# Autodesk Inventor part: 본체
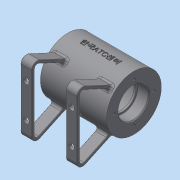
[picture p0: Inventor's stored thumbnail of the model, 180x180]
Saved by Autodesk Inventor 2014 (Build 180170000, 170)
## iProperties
Created: 2021-12
Part Number: 본체
Material: 일반
Document SubType Name: Modeling
Designer: dg
Density: 1 g/cm^3
Appearance: 기본값
Author: dg
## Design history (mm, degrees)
sketch "스케치1"
  geometry: L1 (-35, 0)-(35, 0); L2 (-35, 16)-(-23, 16); L3 (-23, 16)-(-23, 14); L4 (-23, 14)-(-21, 14); L5 (-21, 14)-(-21, 21); L6 (-21, 21)-(21, 21); L7 (21, 21)-(21, 14); L8 (21, 14)-(23, 14); L9 (23, 14)-(23, 16); L10 (23, 16)-(35, 16); L11 (35, 16)-(35, 29); L12 (35, 29)-(-35, 29); L13 (-35, 29)-(-35, 16); 2 further points
  constraints: 26 end point, 9 parallel, 3 collinear, 2 horizontal alignment, 2 perpendicular, 2 vertical alignment, 1 coincident, 1 horizontal, 1 midpoint
  dimensions: "d0" = 70 distance of L1.start L1.end; "d1" = 32 diameter of L2 L1; "d2" = 28 diameter of L4 L1; "d3" = 42 diameter of L6 L1; "d4" = 58 diameter of L12 L1; "d5" = 12 distance of L2.start L2.end; "d7" = 42 distance of L5.end L6.end
revolve "회전1" sketch "스케치1" stored, may be unused: angle "d8" = 90 deg
node "작업 평면1"
sketch "스케치2"
  geometry: L1 (-22.743, -17.993)-(-40, -55); L2 (-40, -55)-(40, -55); L3 (40, -55)-(22.743, -17.993); L4 (-20.574, -20.438)-(-35.291, -52); L5 (-35.291, -52)-(35.291, -52); L6 (35.291, -52)-(20.574, -20.438); A1 r 29 centre (0, 0) between (-22.743, -17.993) and (22.743, -17.993) reference; 1 further point
  constraints: 12 end point, 4 point on circle, 3 parallel, 2 horizontal alignment, 1 horizontal
  dimensions: "d10" = 80 distance of L2.end L1.end; "d11" = 3 distance between parallel lines of L4 L1; "d12" = 3 distance between parallel lines of L3 L6; "d13" = 3 distance between parallel lines of L2 L5; "d14" = 55 distance from line of L2 point (0, 0); "d15" = 65 deg angle of L2 L3
extrude "돌출1" join sketch "스케치2" distance "d16" = 12; taper "d17" = 0 deg
node "작업 평면2"
fillet "모깎기1" dims "d18" = 6, "d19" = 3
sketch "스케치3"
  geometry: C1 r 29 at (0, 0) reference; 1 further point
  constraints: 1 vertical alignment
  dimensions: "d20" = 21 distance of C1.centre point (0, 21)
hole "구멍1" sketch "스케치3" at (0, 21) diameter "d21" = 3.242; stored, may be unused: countersink angle "d25" = 90 deg, drill point angle "d27" = 118 deg; dims "d22" = 8, "d23" = 4, "d24" = 2, "d26" = 10
sketch "스케치4"
  geometry: L1 (0, 0)-(10.945, -30.07); L2 (0, 0)-(0, -48.02); L3 (10.945, -30.07)-(16.583, -28.018); L4 (16.583, -28.018)-(14.601, -22.573); L5 (14.601, -22.573)-(8.963, -24.625)
  constraints: 10 end point, 3 perpendicular, 1 point on line, 1 vertical
  dimensions: "d31" = 32 distance of L1.start L1.end; "d32" = 20 deg angle of L1 L2; "d33" = 12 diameter of L4 L1; "d34" = 5.79433 distance between parallel lines of L3 L5
revolve "회전2" sketch "스케치4" stored, may be unused: angle "d35" = 90 deg
hole "구멍2" diameter "d38" = 4.917; stored, may be unused: countersink angle "d42" = 90 deg, drill point angle "d44" = 118 deg; dims "d36" = 10, "d37" = 10, "d39" = 8, "d40" = 4, "d41" = 2, "d43" = 10
node "작업 평면3"
sketch "스케치5"
  geometry: C1 r 5 at (0, 0); C2 r 1.5 at (0, 0); 1 further point
  constraints: 2 centre point, 2 coincident
  dimensions: "d46" = 10 diameter of C1; "d47" = 3 diameter of C2
extrude "돌출2" join sketch "스케치5" stored distance "d48" = 12; taper "d49" = 0 deg
extrude "돌출3" cut sketch "스케치5" stored distance "d50" = 12; taper "d51" = 0 deg
hole "구멍3" diameter "d54" = 4.917; stored, may be unused: countersink angle "d58" = 90 deg, drill point angle "d60" = 118 deg; dims "d52" = 10, "d53" = 10, "d55" = 6, "d56" = 4, "d57" = 2, "d59" = 8
sketch "스케치6"
  geometry: L1 (0, 61.164)-(0, 0) reference; C1 r 3 at (6, 48.582); C2 r 3 at (6, 12.582); C3 r 3 at (54, 48.582); C4 r 3 at (54, 12.582); 1 further point
  constraints: 4 centre point, 3 equal radius, 2 horizontal alignment, 2 vertical alignment
  dimensions: "d61" = 36 distance of C2.centre C1.centre; "d62" = 6 distance from line of C1.centre L1; "d63" = 48 distance of C3.centre C1.centre; "d64" = 6 diameter of C1; "d65" = 18 vertical distance of point (30, 30.582) C1.centre
extrude "돌출4" cut sketch "스케치6" stored distance "d66" = 12; taper "d67" = 0 deg
fillet "모깎기2" dims "d68" = 0.5
fillet "모깎기3" dims "d69" = 3, "d70" = 1
chamfer "모따기1" distance "d71" = 1; stored, may be unused: second distance "d72" = 2, angle "d73" = 45 deg
fillet "모깎기4" dims "d74" = 0.3, "d75" = 3
node "작업 평면4"
sketch "스케치7"
  geometry: L1 (-35, -29)-(-35, 29) reference; 2 further points
  constraints: 2 coincident, 1 other
  dimensions: "d80" = 35 distance from line of point (0, 0) L1 (derived); "d81" = 29 vertical distance of point (0, 0) L1.end (derived)
feature "엠보싱1" sketch "스케치7" dims "d0" = 70, "d1" = 32, "d2" = 28, "d3" = 42, "d4" = 58, "d5" = 12, "d7" = 42, "d78" = 0.5, "d79" = 0
node "솔리드1"
mirror "대칭1"
pattern_circular "원형 패턴1" dims angle "d29" = 360 deg
mirror "대칭2"
other parameters: "d9" = -5, "d45" = 32
